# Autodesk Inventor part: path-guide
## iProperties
Created: 2004-05
Part Number: path-guide
Document SubType Name: Modeling
Designer: CADCIM Technologies
Manufacturer: Standard
Standards Organization: Custom
Density: 1 g/cm^3
Author: CADCIM Technologies
